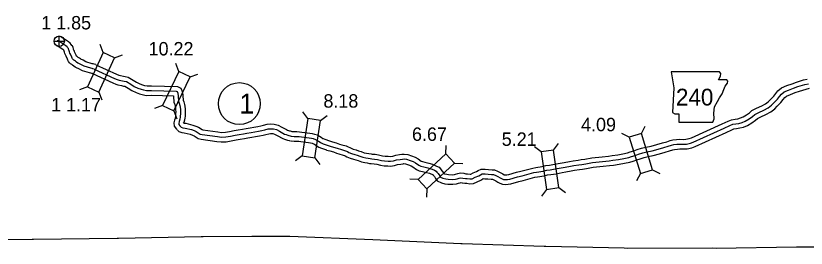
# Model space of a CAD drawing. Extents: x -83719 to 153526, y -11835 to 11446.
# Drawn here: x -5205 to -4375, y -4517 to -4273 of the extents above; entities that cross this region are included whole.
import ezdxf

# ---------------------------------------------------------------- set-up
doc = ezdxf.new("R2010")
doc.units = 0
for name, color, linetype in [('Level 10', 7, 'Continuous'), ('Level 2', 7, 'Continuous'), ('Level 20', 7, 'Continuous'), ('Level 21', 7, 'Continuous'), ('Level 25', 7, 'Continuous'), ('Level 26', 7, 'Continuous'), ('Level 27', 7, 'Continuous'), ('Level 58', 7, 'Continuous'), ('Level 59', 7, 'Continuous')]:
    doc.layers.add(name, color=color, linetype=linetype)

msp = doc.modelspace()

# ---------------------------------------------------------------- linework, layer by layer
at = {"layer": 'Level 10'}
for points in [[(-5121.14, -4324.18), (-5122.94, -4323.67), (-5123.87, -4323.48), (-5124.87, -4323.18), (-5131.46, -4321.23), (-5134.56, -4319.6), (-5136.73, -4318.54), (-5137.31, -4318.21), (-5138.37, -4317.46), (-5139.65, -4316.55), (-5140.72, -4315.77), (-5141.2, -4315.45), (-5141.46, -4315.2), (-5141.88, -4314.34), (-5143.18, -4311.3), (-5143.66, -4310.18), (-5144.11, -4309.08), (-5144.41, -4308.14), (-5144.6, -4307.5), (-5144.92, -4306.19), (-5145.69, -4304.48), (-5146.17, -4303.91), (-5146.9, -4302.88), (-5147.94, -4301.79), (-5149.72, -4300.28), (-5152.84, -4298.25), (-5155.01, -4296.76), (-5156.32, -4295.9), (-5157.24, -4295.36), (-5158.61, -4294.67), (-5160.18, -4294.22)], [(-5124.63, -4333.59), (-5125.31, -4333.39), (-5126.32, -4333.19), (-5127.73, -4332.76), (-5135.23, -4330.55), (-5139.08, -4328.52), (-5141.4, -4327.39), (-5142.68, -4326.66), (-5144.16, -4325.62), (-5145.5, -4324.66), (-5146.43, -4323.98), (-5147.55, -4323.24), (-5148.61, -4322.19), (-5149.84, -4320.96), (-5150.56, -4319.35), (-5150.98, -4318.49), (-5152.36, -4315.25), (-5152.89, -4314.04), (-5153.52, -4312.47), (-5153.97, -4311.07), (-5154.25, -4310.11), (-5154.37, -4309.64), (-5154.64, -4309.25), (-5154.81, -4309.08), (-5155.7, -4308.32), (-5158.4, -4306.56), (-5160.58, -4305.06), (-5161.61, -4304.39), (-5162.03, -4304.14), (-5162.26, -4304.03), (-5162.97, -4303.82)], [(-5121.14, -4324.19), (-5099.42, -4334.14), (-5097.06, -4335.09), (-5095.41, -4335.5), (-5092.06, -4336.38), (-5090.51, -4336.71), (-5087.16, -4337.19)], [(-5124.63, -4333.59), (-5103.38, -4343.33), (-5100.15, -4344.63), (-5097.88, -4345.19), (-5094.36, -4346.12), (-5092.25, -4346.56), (-5090.61, -4346.79)], [(-5087.16, -4337.19), (-5081.85, -4340.42), (-5078.42, -4342.6), (-5075.11, -4344.19), (-5072.06, -4345.22), (-5070.03, -4345.87), (-5067.34, -4346.37), (-5062.7, -4346.34), (-5035.45, -4347.08), (-5031.86, -4348.78)], [(-5090.61, -4346.79), (-5087.13, -4348.91), (-5083.27, -4351.36), (-5078.89, -4353.46), (-5075.19, -4354.72), (-5072.47, -4355.58), (-5068.23, -4356.37), (-5062.8, -4356.34), (-5039.72, -4356.96)], [(-4543.67, -4410.69), (-4538.28, -4409.57), (-4532.27, -4408.07), (-4526.43, -4406.25), (-4521.88, -4404.93), (-4518.27, -4403.81), (-4515.47, -4403.14), (-4511.64, -4402.68), (-4508.47, -4402.45), (-4503.95, -4402.52), (-4501.68, -4402.47), (-4498.18, -4401.68), (-4495.85, -4400.87), (-4463.7, -4386.13), (-4457.47, -4383.3), (-4453.91, -4381.86), (-4450.14, -4381.34), (-4447.29, -4380.82), (-4444.37, -4380.07), (-4441.73, -4378.95), (-4438.12, -4376.78), (-4434.92, -4374.59), (-4432.38, -4372.35), (-4427.5, -4369.94), (-4422.15, -4367.46), (-4418.14, -4365.37), (-4415.29, -4363.11), (-4413.09, -4360.78), (-4409.54, -4357.23), (-4407.45, -4354.48), (-4405.1, -4351.75), (-4401.43, -4348.46), (-4395.73, -4346.09), (-4390.39, -4344.16), (-4385.71, -4342.38), (-4378.21, -4340.16), (-4374.43, -4339.27)], [(-5031.86, -4348.78), (-5030.15, -4352.88), (-5029.66, -4356.82), (-5029.4, -4361.27), (-5028.66, -4363.24), (-5028.17, -4365.85), (-5027.61, -4367.85), (-5027.43, -4371.02), (-5027.3, -4373.62), (-5027.43, -4376.29), (-5027.5, -4378.4), (-5027.8, -4379.92), (-5028.11, -4382.53), (-5028.84, -4384.96), (-5028.93, -4385.35), (-5028.77, -4385.52)], [(-4541.64, -4420.48), (-4536.06, -4419.32), (-4529.58, -4417.71), (-4523.54, -4415.83), (-4518.99, -4414.5), (-4515.62, -4413.46), (-4513.7, -4413), (-4510.68, -4412.63), (-4508.19, -4412.45), (-4503.91, -4412.52), (-4500.45, -4412.44), (-4495.44, -4411.31), (-4492.13, -4410.17), (-4459.54, -4395.23), (-4453.51, -4392.49), (-4451.31, -4391.59), (-4448.55, -4391.22), (-4445.15, -4390.59), (-4441.16, -4389.58), (-4437.17, -4387.88), (-4432.71, -4385.2), (-4428.77, -4382.5), (-4426.77, -4380.74), (-4423.18, -4378.96), (-4417.73, -4376.43), (-4412.67, -4373.8), (-4408.52, -4370.5), (-4405.92, -4367.76), (-4401.98, -4363.81), (-4399.67, -4360.77), (-4397.95, -4358.77), (-4396.03, -4357.05), (-4392.11, -4355.42), (-4386.91, -4353.54), (-4382.5, -4351.86), (-4375.65, -4349.83), (-4371.85, -4348.94)], [(-5039.72, -4356.98), (-5039.62, -4357.73), (-5039.29, -4363.36), (-5038.33, -4365.92), (-5037.92, -4368.12), (-5037.53, -4369.51), (-5037.42, -4371.55), (-5037.31, -4373.62), (-5037.42, -4375.89), (-5037.47, -4377.26), (-5037.68, -4378.35), (-5037.94, -4380.48), (-5038.52, -4382.4), (-5039.19, -4385.35), (-5039.06, -4388.72), (-5036.63, -4391.76), (-5036.06, -4392.37)], [(-5029.39, -4384.96), (-5028.95, -4385.3), (-5028.58, -4385.44), (-5026.5, -4385.69), (-5019.31, -4387.5), (-5016.09, -4388.7), (-5013.3, -4389.8), (-5009.62, -4392.29), (-5008.69, -4392.54), (-4992.91, -4394.7), (-4989.12, -4395.15), (-4985.11, -4395.01), (-4980.81, -4394.35), (-4975.83, -4393.36), (-4971.62, -4392.56), (-4967.07, -4391.7), (-4963.37, -4391.03), (-4959.03, -4390.33)], [(-4959.2, -4390.36), (-4955.11, -4389.55), (-4951.22, -4389.11), (-4947.95, -4388.33), (-4944.99, -4387.63), (-4941.13, -4386.66), (-4937.87, -4386.4), (-4934.04, -4386.52), (-4929.72, -4387.52), (-4925.98, -4389.68), (-4921.03, -4392.34), (-4919.83, -4392.72), (-4917.75, -4393.48), (-4917.1, -4393.7), (-4916.21, -4393.91), (-4915.14, -4394.13), (-4914.53, -4394.28)], [(-5035.44, -4392.93), (-5033.87, -4394.11), (-5031.03, -4395.22), (-5028.31, -4395.55), (-5022.28, -4397.06), (-5019.68, -4398.03), (-5017.99, -4398.7), (-5013.84, -4401.5), (-5010.69, -4402.36), (-4994.18, -4404.61), (-4989.55, -4405.17), (-4984.17, -4404.99), (-4979.07, -4404.2), (-4973.93, -4403.18), (-4969.75, -4402.39), (-4965.24, -4401.53), (-4961.68, -4400.89), (-4957.43, -4400.2)], [(-4957.26, -4400.17), (-4953.58, -4399.44), (-4949.49, -4398.98), (-4945.64, -4398.06), (-4942.62, -4397.34), (-4939.5, -4396.56), (-4937.63, -4396.41), (-4935.33, -4396.48), (-4933.43, -4396.92), (-4930.85, -4398.41), (-4924.92, -4401.61), (-4923.04, -4402.19), (-4921.1, -4402.91), (-4919.87, -4403.32), (-4918.36, -4403.68), (-4917.29, -4403.9), (-4916.83, -4404.01)], [(-4915.33, -4394.16), (-4912.64, -4394.34), (-4910.12, -4394.41), (-4907.26, -4394.59), (-4904.73, -4394.88), (-4901.88, -4395.28), (-4899.41, -4395.62), (-4896.34, -4396.08), (-4893.97, -4396.44), (-4891.63, -4396.92), (-4888.52, -4397.88), (-4886.37, -4399.09), (-4884.6, -4400.27), (-4883, -4401.45), (-4882.53, -4401.74), (-4880.81, -4402.36), (-4875.72, -4404.19)], [(-4916.03, -4404.13), (-4913.12, -4404.33), (-4910.56, -4404.4), (-4908.15, -4404.55), (-4906, -4404.8), (-4903.25, -4405.19), (-4900.84, -4405.52), (-4897.83, -4405.97), (-4895.72, -4406.29), (-4894.12, -4406.62), (-4892.48, -4407.13), (-4891.6, -4407.62), (-4890.34, -4408.46), (-4888.65, -4409.7), (-4886.96, -4410.78), (-4884.19, -4411.77), (-4879.1, -4413.6)], [(-4875.97, -4404.11), (-4872.86, -4405.04), (-4868.82, -4406.13), (-4865.34, -4407.38), (-4863, -4408.11), (-4858.46, -4409.46), (-4856.32, -4410.18), (-4854.69, -4410.93), (-4853.27, -4411.78), (-4851.05, -4412.67), (-4847.85, -4413.62), (-4845.35, -4414.44), (-4842.5, -4415.27), (-4839.31, -4416.49), (-4836.85, -4416.99), (-4834.54, -4417.41), (-4832.29, -4417.81), (-4830.99, -4418.04), (-4827.91, -4418.19), (-4824.34, -4418.79), (-4820.34, -4419.7), (-4817.56, -4420.14), (-4814.12, -4420.22), (-4812.09, -4420.39), (-4809.52, -4420), (-4806.4, -4419.2), (-4802.46, -4418.54), (-4799.85, -4418.15), (-4797.37, -4417.92), (-4793.65, -4418.52), (-4789.65, -4419.9), (-4785.86, -4421.29), (-4782.92, -4423.01), (-4779.59, -4425.33), (-4778.41, -4425.88), (-4775.74, -4426.52), (-4771.49, -4427.59), (-4767.8, -4428.59), (-4766.19, -4429.22), (-4763.41, -4430.47), (-4760.87, -4431.83), (-4759.31, -4433.52), (-4757.79, -4435.39), (-4755.98, -4438.04), (-4755.9, -4438.17), (-4755.1, -4438.52), (-4752.81, -4439.16), (-4750.94, -4439.39), (-4746.7, -4439.57), (-4744.51, -4439.37), (-4743.43, -4439), (-4741.05, -4438.36), (-4738.39, -4437.78), (-4735.03, -4438.07), (-4732.81, -4438.54), (-4731.1, -4438.49), (-4728.26, -4438.96), (-4727.5, -4438.89), (-4725, -4437.74), (-4721.61, -4436.36), (-4719.89, -4435.22), (-4716.63, -4433.65), (-4712.29, -4433.78), (-4708.89, -4433.95), (-4705.26, -4434.35), (-4702.71, -4434.57), (-4699.38, -4435.7), (-4696.6, -4437.22), (-4694.07, -4438.63), (-4692.48, -4439.57), (-4692.14, -4439.72), (-4691.2, -4439.75), (-4689.72, -4439.61), (-4687.71, -4439.25), (-4679.72, -4436.95), (-4674.95, -4435.81), (-4662.53, -4432.55), (-4659.39, -4431.93), (-4652.51, -4430.84), (-4648.75, -4429.99), (-4645, -4429.44), (-4639.63, -4428.65), (-4633.59, -4427.55), (-4629.55, -4426.77), (-4623.99, -4425.73), (-4620.21, -4424.96), (-4614.94, -4424.23), (-4611.65, -4423.76), (-4607.7, -4423.16), (-4600.46, -4421.8), (-4589.71, -4420.71), (-4583, -4419.99), (-4579.17, -4419.52), (-4573.37, -4418.59), (-4568.02, -4417.6), (-4562.99, -4416.59), (-4560.21, -4415.76), (-4556.46, -4414.54), (-4552.91, -4413.31), (-4548.31, -4411.9), (-4543.93, -4410.75)], [(-4878.85, -4413.68), (-4875.6, -4414.66), (-4871.81, -4415.68), (-4868.52, -4416.87), (-4865.91, -4417.67), (-4861.48, -4419), (-4860, -4419.5), (-4859.36, -4419.79), (-4857.75, -4420.76), (-4854.34, -4422.13), (-4850.84, -4423.16), (-4848.32, -4424), (-4845.68, -4424.76), (-4842.1, -4426.12), (-4838.75, -4426.81), (-4836.31, -4427.25), (-4834.02, -4427.66), (-4832.11, -4427.99), (-4828.99, -4428.15), (-4826.27, -4428.61), (-4822.24, -4429.52), (-4818.47, -4430.12), (-4814.64, -4430.21), (-4811.74, -4430.45), (-4807.52, -4429.81), (-4804.33, -4428.99), (-4800.89, -4428.42), (-4798.64, -4428.08), (-4797.72, -4427.99), (-4796.09, -4428.26), (-4793, -4429.32), (-4790.15, -4430.37), (-4788.32, -4431.45), (-4784.59, -4434.03), (-4781.73, -4435.37), (-4778.12, -4436.24), (-4774.01, -4437.26), (-4770.94, -4438.1), (-4770.07, -4438.44), (-4767.82, -4439.45), (-4767.07, -4439.85), (-4766.87, -4440.07), (-4765.81, -4441.37), (-4764.43, -4443.4), (-4762.86, -4446.06), (-4758.44, -4447.97), (-4754.77, -4448.99), (-4751.76, -4449.36), (-4746.47, -4449.58), (-4742.39, -4449.23), (-4740.49, -4448.56), (-4738.69, -4448.08), (-4737.75, -4447.87), (-4736.51, -4447.98), (-4733.71, -4448.58), (-4731.76, -4448.52), (-4728.65, -4449.03), (-4724.88, -4448.7), (-4721.02, -4446.91), (-4716.92, -4445.25), (-4714.94, -4443.94), (-4714.49, -4443.72), (-4712.69, -4443.78), (-4709.68, -4443.92), (-4706.24, -4444.3), (-4704.79, -4444.42), (-4703.42, -4444.89), (-4701.43, -4445.98), (-4699.06, -4447.3), (-4697.02, -4448.51), (-4694.34, -4449.66), (-4690.88, -4449.77), (-4688.37, -4449.52), (-4685.45, -4449.01), (-4677.17, -4446.62), (-4672.51, -4445.51), (-4660.28, -4442.3), (-4657.64, -4441.78), (-4650.61, -4440.67), (-4646.92, -4439.83), (-4643.55, -4439.34), (-4638.01, -4438.52), (-4631.75, -4437.38), (-4627.68, -4436.59), (-4622.07, -4435.54), (-4618.53, -4434.82), (-4613.55, -4434.14), (-4610.18, -4433.65), (-4606.02, -4433.01), (-4599.03, -4431.71), (-4588.67, -4430.65), (-4581.86, -4429.92), (-4577.77, -4429.42), (-4571.67, -4428.45), (-4566.11, -4427.42), (-4560.57, -4426.3), (-4557.24, -4425.31), (-4553.28, -4424.02), (-4549.8, -4422.82), (-4545.57, -4421.52), (-4541.39, -4420.42)]]:
    msp.add_lwpolyline(points, dxfattribs=at)
at = {"layer": 'Level 2'}
for points in [[(-5402.09, -4511.42), (-5366.9, -4512.56), (-5275.81, -4507.98), (-5274.74, -4508.11), (-5188.1, -4507.07), (-5186.56, -4507.13), (-5098.78, -4506.28), (-5097.22, -4506.14), (-5010.45, -4504.4), (-5008.61, -4504.35), (-4957.4, -4504.13)], [(-4957.4, -4504.13), (-4919.56, -4503.96), (-4917.36, -4504.16), (-4830.3, -4507.52), (-4737.87, -4511.88), (-4736.7, -4511.79), (-4650.39, -4514.4), (-4648.66, -4514.34), (-4566.66, -4516.43), (-4563.06, -4516.62), (-4473.92, -4516.38), (-4469.88, -4516.53), (-4385.62, -4515.36), (-4383.52, -4515.36), (-4328.12, -4515.28)]]:
    msp.add_lwpolyline(points, dxfattribs=at)
at = {"layer": 'Level 20'}
for p, q in [((-5113.39, -4311.46), (-5116.45, -4303.21)), ((-5101.39, -4316.96), (-5093.14, -4313.89)), ((-5034.11, -4331.33), (-5037.07, -4323.04)), ((-5022.19, -4336.99), (-5013.9, -4334.03)), ((-5129.88, -4347.46), (-5138.13, -4350.53)), ((-5117.88, -4352.96), (-5114.82, -4361.21)), ((-5051.09, -4367.1), (-5059.38, -4370.06)), ((-5039.17, -4372.76), (-5036.21, -4381.05)), ((-4898.52, -4380.79), (-4903.74, -4373.71)), ((-4885.46, -4382.75), (-4878.38, -4377.52)), ((-4548.54, -4396.48), (-4544.42, -4388.7)), ((-4561.15, -4400.37), (-4568.93, -4396.25)), ((-4753.66, -4417.8), (-4753.3, -4409.01)), ((-4653.76, -4415.76), (-4660.81, -4410.49)), ((-4640.69, -4413.87), (-4635.43, -4406.82)), ((-4904.4, -4419.95), (-4911.48, -4425.18)), ((-4891.35, -4421.91), (-4886.12, -4428.99)), ((-4744.72, -4427.51), (-4735.93, -4427.87)), ((-4549.49, -4438.21), (-4553.61, -4445.99)), ((-4536.88, -4434.33), (-4529.1, -4438.44)), ((-4782.79, -4444.63), (-4791.58, -4444.27)), ((-4773.85, -4454.34), (-4774.21, -4463.13)), ((-4648.09, -4454.95), (-4653.36, -4462)), ((-4635.03, -4453.06), (-4627.98, -4458.33))]:
    msp.add_line(p, q, dxfattribs=at)
for points in [[(-5117.88, -4352.96), (-5101.39, -4316.96), (-5113.39, -4311.46), (-5129.88, -4347.46)], [(-5039.17, -4372.76), (-5022.19, -4336.99), (-5034.11, -4331.33), (-5051.09, -4367.1)], [(-4898.52, -4380.79), (-4904.4, -4419.95), (-4891.35, -4421.91), (-4885.46, -4382.75)], [(-4536.88, -4434.33), (-4548.54, -4396.48), (-4561.15, -4400.37), (-4549.49, -4438.21)], [(-4773.85, -4454.34), (-4744.72, -4427.51), (-4753.66, -4417.8), (-4782.79, -4444.63)], [(-4653.76, -4415.76), (-4648.09, -4454.95), (-4635.03, -4453.06), (-4640.69, -4413.87)]]:
    msp.add_lwpolyline(points, close=True, dxfattribs=at)
at = {"layer": 'Level 21'}
msp.add_lwpolyline([(-4517.08, -4331.64), (-4514.54, -4348.56), (-4515.67, -4374.22), (-4513.41, -4375.63), (-4509.18, -4375.63), (-4509.18, -4384.65), (-4473.65, -4384.65), (-4471.96, -4380.98), (-4472.53, -4375.06), (-4471.68, -4368.29), (-4468.58, -4362.94), (-4466.61, -4358.99), (-4463.79, -4354.76), (-4462.09, -4350.25), (-4460.68, -4346.58), (-4458.15, -4343.48), (-4457.58, -4341.51), (-4458.71, -4340.1), (-4467.45, -4340.1), (-4465.48, -4336.15), (-4465.2, -4333.61), (-4466.37, -4331.66)], close=True, dxfattribs=at)
at = {"layer": 'Level 26'}
for p, q in [((-5159.6, -4305.05), (-5159.6, -4294.22)), ((-5165.02, -4299.64), (-5154.18, -4299.64))]:
    msp.add_line(p, q, dxfattribs=at)
msp.add_circle((-5159.6, -4299.64), 5.42, dxfattribs=at)
at = {"layer": 'Level 27'}
msp.add_circle((-4970.49, -4365.02), 22, dxfattribs=at)
at = {"layer": 'Level 59'}
for points in [[(-5122.89, -4328.88), (-5124.13, -4328.53), (-5125.09, -4328.33), (-5126.3, -4327.97), (-5133.34, -4325.89), (-5136.82, -4324.06), (-5139.06, -4322.97), (-5140, -4322.44), (-5141.27, -4321.54), (-5142.57, -4320.61), (-5143.58, -4319.88), (-5144.38, -4319.35), (-5145.08, -4318.65), (-5145.65, -4318.08), (-5146.02, -4317.25), (-5146.43, -4316.41), (-5147.77, -4313.27), (-5148.28, -4312.11), (-5148.82, -4310.77), (-5149.19, -4309.6), (-5149.42, -4308.8), (-5149.66, -4307.83), (-5149.96, -4307.17), (-5150.13, -4306.97), (-5150.77, -4306.07), (-5151.37, -4305.43), (-5152.71, -4304.3), (-5155.62, -4302.41), (-5157.79, -4300.91), (-5158.97, -4300.15), (-5159.63, -4299.75), (-5160.44, -4299.35), (-5161.57, -4299.02)], [(-5122.89, -4328.88), (-5101.4, -4338.73), (-5098.6, -4339.86), (-5096.64, -4340.35), (-5093.21, -4341.25), (-5091.38, -4341.63), (-5088.88, -4341.99)], [(-5088.88, -4341.99), (-5084.49, -4344.66), (-5080.84, -4346.98), (-5077, -4348.82), (-5073.63, -4349.97), (-5071.25, -4350.73), (-5067.78, -4351.37), (-5062.75, -4351.34), (-5036.64, -4352.05), (-5035.74, -4352.47)], [(-4542.66, -4415.58), (-4537.17, -4414.44), (-4530.93, -4412.89), (-4524.98, -4411.04), (-4520.43, -4409.71), (-4516.95, -4408.63), (-4514.59, -4408.07), (-4511.16, -4407.65), (-4508.33, -4407.45), (-4503.93, -4407.52), (-4501.06, -4407.45), (-4496.81, -4406.49), (-4493.99, -4405.52), (-4461.62, -4390.68), (-4455.49, -4387.9), (-4452.61, -4386.73), (-4449.35, -4386.28), (-4446.22, -4385.71), (-4442.76, -4384.83), (-4439.45, -4383.41), (-4435.42, -4380.99), (-4431.85, -4378.54), (-4429.58, -4376.54), (-4425.34, -4374.45), (-4419.94, -4371.95), (-4415.4, -4369.58), (-4411.91, -4366.8), (-4409.51, -4364.27), (-4405.76, -4360.52), (-4403.56, -4357.62), (-4401.53, -4355.26), (-4398.73, -4352.76), (-4393.92, -4350.76), (-4388.65, -4348.85), (-4384.1, -4347.12), (-4376.93, -4344.99), (-4373.14, -4344.11)], [(-5035.74, -4352.47), (-5035.03, -4354.17), (-5034.64, -4357.28), (-5034.34, -4362.32), (-5033.5, -4364.58), (-5033.05, -4366.98), (-5032.57, -4368.68), (-5032.42, -4371.28), (-5032.31, -4373.62), (-5032.43, -4376.09), (-5032.48, -4377.83), (-5032.74, -4379.13), (-5033.03, -4381.5), (-5033.68, -4383.68), (-5034.17, -4385.82), (-5034.13, -4386.89), (-5032.85, -4388.48), (-5032.42, -4388.95)], [(-5032.42, -4388.95), (-5031.41, -4389.71), (-5029.81, -4390.33), (-5027.4, -4390.62), (-5020.79, -4392.28), (-5017.89, -4393.36), (-5015.65, -4394.25), (-5011.73, -4396.9), (-5009.69, -4397.45), (-4993.54, -4399.66), (-4989.34, -4400.16), (-4984.64, -4400), (-4979.94, -4399.27), (-4974.88, -4398.27), (-4970.69, -4397.48), (-4966.16, -4396.61), (-4962.53, -4395.96), (-4958.23, -4395.26)], [(-4958.23, -4395.26), (-4954.35, -4394.5), (-4950.35, -4394.04), (-4946.8, -4393.2), (-4943.81, -4392.49), (-4940.32, -4391.61), (-4937.75, -4391.41), (-4934.68, -4391.5), (-4931.57, -4392.22), (-4928.42, -4394.05), (-4922.98, -4396.97), (-4921.44, -4397.45), (-4919.43, -4398.19), (-4918.49, -4398.51), (-4917.28, -4398.8), (-4916.21, -4399.02), (-4915.68, -4399.14)], [(-4915.68, -4399.14), (-4912.88, -4399.34), (-4910.34, -4399.4), (-4907.71, -4399.57), (-4905.37, -4399.84), (-4902.56, -4400.23), (-4900.13, -4400.57), (-4897.09, -4401.03), (-4894.85, -4401.36), (-4892.88, -4401.77), (-4890.5, -4402.5), (-4888.99, -4403.35), (-4887.47, -4404.36), (-4885.82, -4405.58), (-4884.75, -4406.26), (-4882.5, -4407.06), (-4877.41, -4408.9)], [(-4877.41, -4408.9), (-4874.23, -4409.85), (-4870.32, -4410.9), (-4866.93, -4412.12), (-4864.46, -4412.89), (-4859.97, -4414.23), (-4858.16, -4414.84), (-4857.02, -4415.36), (-4855.51, -4416.27), (-4852.69, -4417.4), (-4849.35, -4418.39), (-4846.83, -4419.22), (-4844.09, -4420.02), (-4840.71, -4421.31), (-4837.8, -4421.9), (-4835.42, -4422.33), (-4833.15, -4422.74), (-4831.55, -4423.02), (-4828.45, -4423.17), (-4825.31, -4423.7), (-4821.29, -4424.61), (-4818.02, -4425.13), (-4814.38, -4425.22), (-4811.91, -4425.42), (-4808.52, -4424.91), (-4805.36, -4424.1), (-4801.67, -4423.48), (-4799.24, -4423.11), (-4797.55, -4422.96), (-4794.87, -4423.39), (-4791.32, -4424.61), (-4788.01, -4425.83), (-4785.62, -4427.23), (-4782.09, -4429.68), (-4780.07, -4430.62), (-4776.93, -4431.38), (-4772.75, -4432.42), (-4769.37, -4433.35), (-4768.13, -4433.83), (-4765.61, -4434.96), (-4763.97, -4435.84), (-4763.09, -4436.8), (-4761.8, -4438.38), (-4760.2, -4440.72), (-4759.38, -4442.11), (-4756.77, -4443.25), (-4753.79, -4444.07), (-4751.35, -4444.37), (-4746.58, -4444.58), (-4743.45, -4444.3), (-4741.96, -4443.78), (-4739.87, -4443.22), (-4738.07, -4442.83), (-4735.77, -4443.03), (-4733.26, -4443.56), (-4731.43, -4443.5), (-4728.45, -4444), (-4726.19, -4443.8), (-4723.01, -4442.32), (-4719.26, -4440.81), (-4717.41, -4439.58), (-4715.56, -4438.69), (-4712.49, -4438.78), (-4709.29, -4438.94), (-4705.75, -4439.32), (-4703.75, -4439.5), (-4701.4, -4440.3), (-4699.02, -4441.6), (-4696.57, -4442.97), (-4694.75, -4444.04), (-4693.24, -4444.69), (-4691.04, -4444.76), (-4689.04, -4444.57), (-4686.58, -4444.13), (-4678.45, -4441.79), (-4673.73, -4440.66), (-4661.4, -4437.42), (-4658.51, -4436.85), (-4651.56, -4435.76), (-4647.84, -4434.91), (-4644.28, -4434.39), (-4638.82, -4433.58), (-4632.67, -4432.47), (-4628.61, -4431.68), (-4623.03, -4430.64), (-4619.37, -4429.89), (-4614.25, -4429.18), (-4610.92, -4428.71), (-4606.86, -4428.09), (-4599.74, -4426.76), (-4589.19, -4425.68), (-4582.43, -4424.95), (-4578.47, -4424.47), (-4572.52, -4423.52), (-4567.06, -4422.51), (-4561.78, -4421.44), (-4558.72, -4420.53), (-4554.87, -4419.28), (-4551.36, -4418.07), (-4546.94, -4416.71), (-4542.66, -4415.58)]]:
    msp.add_lwpolyline(points, dxfattribs=at)

# ---------------------------------------------------------------- texts
at = {"layer": 'Level 21'}
msp.add_text('240', height=17.6, dxfattribs=at).set_placement((-4512.21, -4367.01))
at = {"layer": 'Level 25'}
msp.add_text('1 1.85', height=14.08, dxfattribs=at).set_placement((-5178.5, -4287.25))
at = {"layer": 'Level 27'}
msp.add_text('1', height=21.12, dxfattribs=at).set_placement((-4970.49, -4375.58))
at = {"layer": 'Level 58'}
for s, p in [('10.22', (-5065.75, -4314.52)), ('8.18', (-4882.25, -4369.26)), ('1 1.17', (-5168.05, -4373.21)), ('4.09', (-4611.79, -4394.01)), ('6.67', (-4789.27, -4404.08)), ('5.21', (-4695.08, -4409.34))]:
    msp.add_text(s, height=14.08, dxfattribs=at).set_placement(p)

doc.saveas('drawing.dxf')
